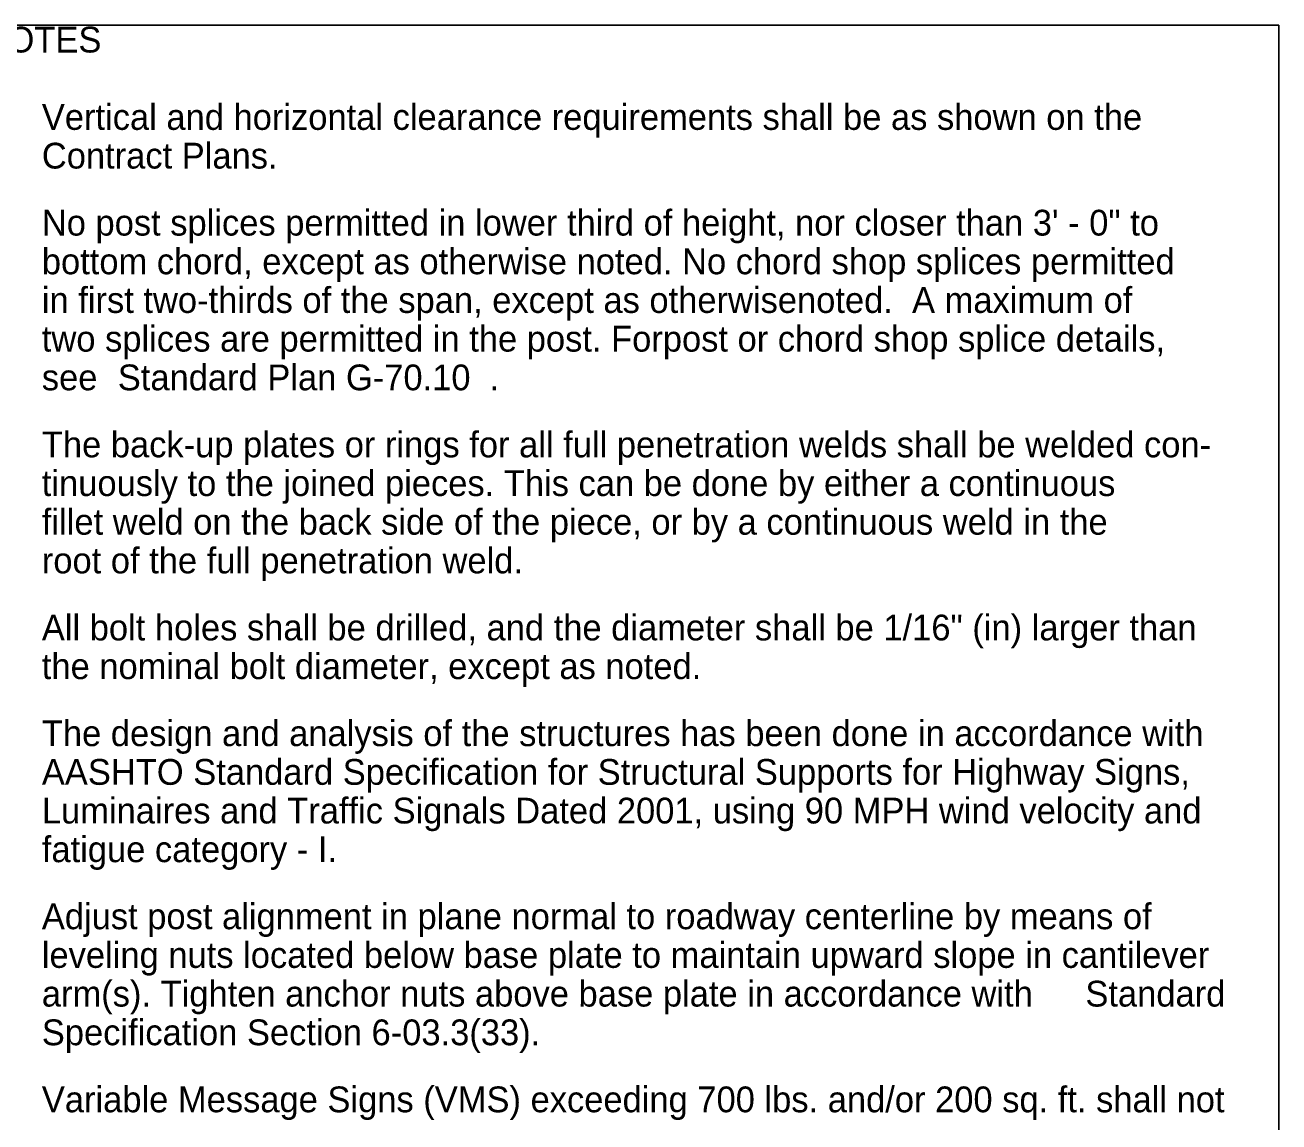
# Model space of a CAD drawing. Extents: x 99862 to 104211, y 98939 to 111076.
# Drawn here: x 102178 to 103150, y 101224 to 102075 of the extents above; entities that cross this region are included whole.
import ezdxf

# ---------------------------------------------------------------- set-up
doc = ezdxf.new("R2010")
doc.units = 0
doc.layers.add('Level 20', color=7, linetype='Continuous')
doc.layers.add('Level 60', color=7, linetype='Continuous')

msp = doc.modelspace()

# ---------------------------------------------------------------- linework, layer by layer
at = {"layer": 'Level 60'}
for p, q in [((103150, 102075), (100000, 102075)), ((103150, 100000), (103150, 102075))]:
    msp.add_line(p, q, dxfattribs=at)

# ---------------------------------------------------------------- texts
at = {"layer": 'Level 20'}
for s, p in [('NOTES', (102144.66, 102053.72)), ('Vertical and horizontal clearance requirements shall be as shown on the ', (102190.57, 101993.72)), ('Contract Plans.', (102190.57, 101963.72)), ('No post splices permitted in lower third of height, nor closer than 3\' - 0" to ', (102190.57, 101911.72)), ('bottom chord, except as otherwise noted. No chord shop splices permitted ', (102190.57, 101881.72)), ('in first two-thirds of the span, except as otherwisenoted.  A maximum of ', (102190.57, 101851.72)), ('two splices are permitted in the post. Forpost or chord shop splice details, ', (102190.57, 101821.72)), ('Standard Plan G-70.10', (102249.49, 101791.72)), ('see ', (102190.57, 101791.72)), ('.', (102537.85, 101791.72)), ('The back-up plates or rings for all full penetration welds shall be welded con-', (102190.57, 101739.72)), ('tinuously to the joined pieces. This can be done by either a continuous ', (102190.57, 101709.72)), ('fillet weld on the back side of the piece, or by a continuous weld in the ', (102190.57, 101679.72)), ('root of the full penetration weld.', (102190.57, 101649.72)), ('All bolt holes shall be drilled, and the diameter shall be 1/16" (in) larger than ', (102190.57, 101597.72)), ('the nominal bolt diameter, except as noted.', (102190.57, 101567.72)), ('The design and analysis of the structures has been done in accordance with ', (102190.57, 101515.72)), ('AASHTO Standard Specification for Structural Supports for Highway Signs, ', (102190.57, 101485.72)), ('Luminaires and Traffic Signals Dated 2001, using 90 MPH wind velocity and ', (102190.57, 101455.72)), ('fatigue category - I.', (102190.57, 101425.72)), ('Adjust post alignment in plane normal to roadway centerline by means of ', (102190.57, 101373.72)), ('leveling nuts located below base plate to maintain upward slope in cantilever ', (102190.57, 101343.72)), ('arm(s). Tighten anchor nuts above base plate in accordance with ', (102190.57, 101313.72)), ('Standard ', (102999.89, 101313.72)), ('Specification Section 6-03.3(33).', (102190.57, 101283.72)), ('Variable Message Signs (VMS) exceeding 700 lbs. and/or 200 sq. ft. shall not ', (102190.57, 101231.72))]:
    msp.add_text(s, height=20, dxfattribs=at).set_placement(p)

doc.saveas('drawing.dxf')
